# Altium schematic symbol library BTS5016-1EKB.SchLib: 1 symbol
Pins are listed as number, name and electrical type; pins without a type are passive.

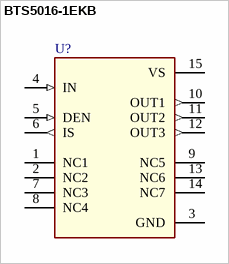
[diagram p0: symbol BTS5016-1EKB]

## BTS5016-1EKB
designator U?  (value not drawn)
Smart High-Side Power Switch, Single Channel, 16 mOhm, PROFET +12V; Manufacturer: Infineon Technologies
footprint SOIC127P600X170-15N
pins: 1 NC1 "Not Connected; No internal connection to the chip.", 2 NC2 "Not Connected; No internal connection to the chip.", 3 GND (power) "Ground", 4 IN (in) "Input channel ; Input signal for channel activation.", 5 DEN (in) "Diagnostic Enable; Digital signal to enable/disable the diagnosis of the device.", 6 IS (out) "Sense; Sense current of the selected channel.", 7 NC3 "Not Connected; No internal connection to the chip.", 8 NC4 "Not Connected; No internal connection to the chip.", 9 NC5 "Not Connected; No internal connection to the chip.", 10 OUT1 (out) "Output ; Protected high side power output channel.", 11 OUT2 (out) "Output ; Protected high side power output channel.", 12 OUT3 (out) "Output ; Protected high side power output channel.", 13 NC6 "Not Connected; No internal connection to the chip.", 14 NC7 "Not Connected; No internal connection to the chip.", 15 VS (power) "Voltage Supply; Battery voltage"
